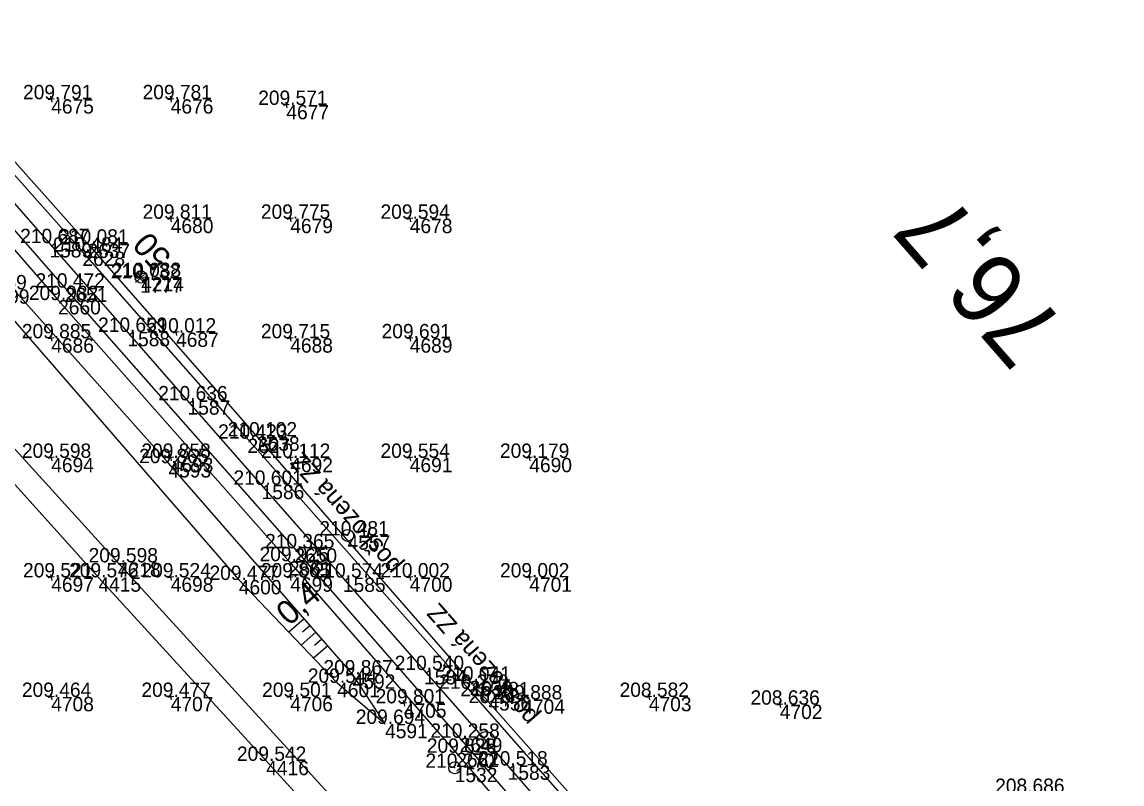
# Model space of a CAD drawing. Extents: x -556590 to -554855, y -1137918 to -1135717.
# Drawn here: x -555142.4 to -555050.4, y -1137077.3 to -1137013.5 of the extents above; entities that cross this region are included whole.
import ezdxf

# ---------------------------------------------------------------- set-up
doc = ezdxf.new("R2010")
doc.units = 0
for name, color, linetype in [('Vrstva 1', 7, 'Continuous'), ('Vrstva 11', 7, 'Continuous'), ('Vrstva 4', 7, 'Continuous'), ('Vrstva 48', 7, 'Continuous'), ('Vrstva 49', 7, 'Continuous'), ('Vrstva 50', 7, 'Continuous'), ('Vrstva 51', 7, 'Continuous'), ('Vrstva 60', 7, 'Continuous'), ('Vrstva 61', 7, 'Continuous'), ('Vrstva 7', 7, 'Continuous')]:
    doc.layers.add(name, color=color, linetype=linetype)

msp = doc.modelspace()

# ---------------------------------------------------------------- linework, layer by layer
at = {"layer": 'Vrstva 1'}
msp.add_lwpolyline([(-555050.414, -1137138.83), (-555056.682, -1137130.254), (-555062.877, -1137122.118), (-555068.951, -1137114.438), (-555075.468, -1137106.449), (-555082.42, -1137098.163), (-555087.974, -1137091.657), (-555094.849, -1137083.708), (-555101.808, -1137075.734), (-555108.81, -1137067.75), (-555115.592, -1137060.018), (-555122.396, -1137052.251), (-555128.594, -1137045.188), (-555133.626, -1137039.462), (-555140.146, -1137032.037), (-555146.394, -1137024.923)], dxfattribs=at)
at = {"layer": 'Vrstva 11'}
for p, q in [((-555132.809, -1137034.495), (-555132.145, -1137035.251)), ((-555132.061, -1137034.592), (-555132.763, -1137034.547)), ((-555131.987, -1137034.973), (-555132.414, -1137034.945))]:
    msp.add_line(p, q, dxfattribs=at)
msp.add_circle((-555132.477, -1137034.873), 0.503, dxfattribs=at)
msp.add_arc((-555132.477, -1137034.873), 0.503, 311.28684, 131.28684, dxfattribs=at)
at = {"layer": 'Vrstva 4'}
for points in [[(-555197.709, -1136962.437), (-555182.891, -1136979.591), (-555167.362, -1136997.627), (-555155.127, -1137011.646), (-555136.972, -1137032.08), (-555122.785, -1137048.208), (-555104.987, -1137068.646), (-555091.678, -1137083.676), (-555079.551, -1137098.027), (-555070.164, -1137109.439)], [(-555070.591, -1137109.654), (-555080.274, -1137097.941), (-555091.957, -1137084.274), (-555105.08, -1137069.321), (-555123.584, -1137048.396), (-555137.389, -1137032.746), (-555155.764, -1137012.076), (-555167.706, -1136998.175), (-555183.54, -1136980.02), (-555198.389, -1136963.208)], [(-555092.816, -1137089.456), (-555093.053, -1137088.239), (-555105.822, -1137073.42), (-555119.654, -1137057.568), (-555138.868, -1137035.761), (-555157.027, -1137015.002), (-555173.15, -1136997.195), (-555186.763, -1136981.447), (-555200.761, -1136965.356)], [(-555201.621, -1136965.878), (-555186.882, -1136982.839), (-555173.619, -1136998.021), (-555158.079, -1137015.373), (-555139.421, -1137036.799), (-555120.117, -1137058.648), (-555106.12, -1137074.669), (-555093.927, -1137088.885), (-555092.816, -1137089.456)]]:
    msp.add_lwpolyline(points, dxfattribs=at)
at = {"layer": 'Vrstva 48'}
for p, q in [((-555118.835, -1137063.462), (-555120.126, -1137064.588)), ((-555117.849, -1137064.593), (-555119.088, -1137065.673)), ((-555118.342, -1137064.027), (-555118.974, -1137064.579)), ((-555116.863, -1137065.723), (-555118.05, -1137066.759)), ((-555117.356, -1137065.158), (-555117.962, -1137065.687))]:
    msp.add_line(p, q, dxfattribs=at)
at = {"layer": 'Vrstva 49'}
for p, q in [((-555140.047, -1137019.754), (-555139.953, -1137020.246)), ((-555130.047, -1137019.754), (-555129.953, -1137020.246)), ((-555139.754, -1137019.953), (-555140.246, -1137020.047)), ((-555129.754, -1137019.953), (-555130.246, -1137020.047)), ((-555120.079, -1137020.43), (-555120.571, -1137020.524)), ((-555120.372, -1137020.231), (-555120.278, -1137020.723)), ((-555130.047, -1137029.754), (-555129.953, -1137030.246)), ((-555120.047, -1137029.754), (-555119.953, -1137030.246)), ((-555110.047, -1137029.754), (-555109.953, -1137030.246)), ((-555129.754, -1137029.953), (-555130.246, -1137030.047)), ((-555119.754, -1137029.953), (-555120.246, -1137030.047)), ((-555109.754, -1137029.953), (-555110.246, -1137030.047)), ((-555139.754, -1137039.953), (-555140.246, -1137040.047)), ((-555140.047, -1137039.754), (-555139.953, -1137040.246)), ((-555129.308, -1137039.467), (-555129.8, -1137039.561)), ((-555129.601, -1137039.268), (-555129.507, -1137039.76)), ((-555119.754, -1137039.953), (-555120.246, -1137040.047)), ((-555120.047, -1137039.754), (-555119.953, -1137040.246)), ((-555109.754, -1137039.953), (-555110.246, -1137040.047)), ((-555110.047, -1137039.754), (-555109.953, -1137040.246)), ((-555139.754, -1137049.953), (-555140.246, -1137050.047)), ((-555140.047, -1137049.754), (-555139.953, -1137050.246)), ((-555129.754, -1137049.953), (-555130.246, -1137050.047)), ((-555130.047, -1137049.754), (-555129.953, -1137050.246)), ((-555119.754, -1137049.953), (-555120.246, -1137050.047)), ((-555120.047, -1137049.754), (-555119.953, -1137050.246)), ((-555109.754, -1137049.953), (-555110.246, -1137050.047)), ((-555110.047, -1137049.754), (-555109.953, -1137050.246)), ((-555099.754, -1137049.953), (-555100.246, -1137050.047)), ((-555100.047, -1137049.754), (-555099.953, -1137050.246)), ((-555139.754, -1137059.953), (-555140.246, -1137060.047)), ((-555140.047, -1137059.754), (-555139.953, -1137060.246)), ((-555129.754, -1137059.953), (-555130.246, -1137060.047)), ((-555130.047, -1137059.754), (-555129.953, -1137060.246)), ((-555119.754, -1137059.953), (-555120.246, -1137060.047)), ((-555120.047, -1137059.754), (-555119.953, -1137060.246)), ((-555109.754, -1137059.953), (-555110.246, -1137060.047)), ((-555110.047, -1137059.754), (-555109.953, -1137060.246)), ((-555099.754, -1137059.953), (-555100.246, -1137060.047)), ((-555100.047, -1137059.754), (-555099.953, -1137060.246)), ((-555139.754, -1137069.953), (-555140.246, -1137070.047)), ((-555140.047, -1137069.754), (-555139.953, -1137070.246)), ((-555129.754, -1137069.953), (-555130.246, -1137070.047)), ((-555130.047, -1137069.754), (-555129.953, -1137070.246)), ((-555119.754, -1137069.953), (-555120.246, -1137070.047)), ((-555120.047, -1137069.754), (-555119.953, -1137070.246)), ((-555110.547, -1137070.291), (-555110.453, -1137070.783)), ((-555100.345, -1137070.16), (-555100.837, -1137070.254)), ((-555100.638, -1137069.961), (-555100.544, -1137070.453)), ((-555089.754, -1137069.953), (-555090.246, -1137070.047)), ((-555090.047, -1137069.754), (-555089.953, -1137070.246)), ((-555079.092, -1137070.401), (-555078.998, -1137070.893)), ((-555110.254, -1137070.49), (-555110.746, -1137070.584)), ((-555078.799, -1137070.6), (-555079.291, -1137070.694))]:
    msp.add_line(p, q, dxfattribs=at)
for points in [[(-555112.067, -1137072.254), (-555114.775, -1137068.117), (-555130.188, -1137050.444), (-555147.188, -1137031.407), (-555156.083, -1137021.917), (-555158.122, -1137020.767), (-555161.258, -1137019.606)], [(-555161.258, -1137019.606), (-555157.188, -1137022.91), (-555145.389, -1137035.904), (-555124.304, -1137060.218), (-555116.079, -1137068.82), (-555112.067, -1137072.254)]]:
    msp.add_lwpolyline(points, dxfattribs=at)
at = {"layer": 'Vrstva 50'}
for p, q in [((-555115.238, -1137056.45), (-555115.172, -1137056.526)), ((-555103.389, -1137069.98), (-555103.455, -1137069.904))]:
    msp.add_line(p, q, dxfattribs=at)
for centre in [(-555115.205, -1137056.488), (-555103.422, -1137069.942)]:
    msp.add_circle(centre, 0.5, dxfattribs=at)
at = {"layer": 'Vrstva 51'}
for points in [[(-555106.827, -1137103.209), (-555101.481, -1137098.096), (-555108.132, -1137090.546), (-555122.012, -1137075.348), (-555136.05, -1137059.997), (-555146.035, -1137048.936), (-555160.294, -1137033.391), (-555175.97, -1137016.16), (-555195.056, -1136995.091), (-555213.136, -1136975.387), (-555223.605, -1136963.802), (-555230.94, -1136955.939), (-555232.118, -1136955.037), (-555233.547, -1136954.632), (-555234.935, -1136954.442), (-555237.794, -1136954.661), (-555240.108, -1136957.322), (-555245.31, -1136962.604), (-555254.296, -1136971.783)], [(-555062.452, -1137139.044), (-555068.645, -1137131.182), (-555075.159, -1137122.841), (-555082.95, -1137112.848), (-555097.37, -1137094.105), (-555099.977, -1137096.599), (-555114.804, -1137080.276), (-555134.417, -1137058.746), (-555153.981, -1137037.247)]]:
    msp.add_lwpolyline(points, dxfattribs=at)
at = {"layer": 'Vrstva 60'}
for p, q in [((-555140, -1137020), (-555140, -1137020)), ((-555130, -1137020), (-555130, -1137020)), ((-555120.325, -1137020.477), (-555120.325, -1137020.477)), ((-555130, -1137030), (-555130, -1137030)), ((-555120, -1137030), (-555120, -1137030)), ((-555110, -1137030), (-555110, -1137030)), ((-555140.146, -1137032.037), (-555140.146, -1137032.037)), ((-555136.972, -1137032.08), (-555136.972, -1137032.08)), ((-555137.389, -1137032.746), (-555137.389, -1137032.746)), ((-555132.564, -1137034.992), (-555132.564, -1137034.992)), ((-555132.477, -1137034.873), (-555132.477, -1137034.873)), ((-555138.868, -1137035.761), (-555138.868, -1137035.761)), ((-555139.421, -1137036.799), (-555139.421, -1137036.799)), ((-555140, -1137040), (-555140, -1137040)), ((-555133.626, -1137039.462), (-555133.626, -1137039.462)), ((-555129.554, -1137039.514), (-555129.554, -1137039.514)), ((-555120, -1137040), (-555120, -1137040)), ((-555110, -1137040), (-555110, -1137040)), ((-555128.594, -1137045.188), (-555128.594, -1137045.188)), ((-555122.785, -1137048.208), (-555122.785, -1137048.208)), ((-555123.584, -1137048.396), (-555123.584, -1137048.396)), ((-555140, -1137050), (-555140, -1137050)), ((-555130, -1137050), (-555130, -1137050)), ((-555120, -1137050), (-555120, -1137050)), ((-555110, -1137050), (-555110, -1137050)), ((-555100, -1137050), (-555100, -1137050)), ((-555130.188, -1137050.444), (-555130.188, -1137050.444)), ((-555122.396, -1137052.251), (-555122.396, -1137052.251)), ((-555115.205, -1137056.488), (-555115.205, -1137056.488)), ((-555119.654, -1137057.568), (-555119.654, -1137057.568)), ((-555134.417, -1137058.746), (-555134.417, -1137058.746)), ((-555120.117, -1137058.648), (-555120.117, -1137058.648)), ((-555140, -1137060), (-555140, -1137060)), ((-555136.05, -1137059.997), (-555136.05, -1137059.997)), ((-555130, -1137060), (-555130, -1137060)), ((-555124.304, -1137060.218), (-555124.304, -1137060.218)), ((-555120, -1137060), (-555120, -1137060)), ((-555115.592, -1137060.018), (-555115.592, -1137060.018)), ((-555110, -1137060), (-555110, -1137060)), ((-555100, -1137060), (-555100, -1137060)), ((-555114.775, -1137068.117), (-555114.775, -1137068.117)), ((-555108.81, -1137067.75), (-555108.81, -1137067.75)), ((-555116.079, -1137068.82), (-555116.079, -1137068.82)), ((-555105.08, -1137069.321), (-555105.08, -1137069.321)), ((-555104.987, -1137068.646), (-555104.987, -1137068.646)), ((-555140, -1137070), (-555140, -1137070)), ((-555130, -1137070), (-555130, -1137070)), ((-555120, -1137070), (-555120, -1137070)), ((-555103.422, -1137069.942), (-555103.422, -1137069.942)), ((-555100.591, -1137070.207), (-555100.591, -1137070.207)), ((-555090, -1137070), (-555090, -1137070)), ((-555110.5, -1137070.537), (-555110.5, -1137070.537)), ((-555079.045, -1137070.647), (-555079.045, -1137070.647)), ((-555112.067, -1137072.254), (-555112.067, -1137072.254)), ((-555105.822, -1137073.42), (-555105.822, -1137073.42)), ((-555106.12, -1137074.669), (-555106.12, -1137074.669)), ((-555122.012, -1137075.348), (-555122.012, -1137075.348)), ((-555106.24, -1137075.93), (-555106.24, -1137075.93)), ((-555101.808, -1137075.734), (-555101.808, -1137075.734))]:
    msp.add_line(p, q, dxfattribs=at)
at = {"layer": 'Vrstva 7'}
for p, q in [((-555132.188, -1137034.662), (-555132.94, -1137035.322)), ((-555132.894, -1137034.616), (-555132.234, -1137035.368)), ((-555106.19, -1137075.93), (-555106.29, -1137075.93))]:
    msp.add_line(p, q, dxfattribs=at)
for centre, radius in [((-555103.638, -1137073.648), 0.75), ((-555106.24, -1137075.93), 0.5)]:
    msp.add_circle(centre, radius, dxfattribs=at)

# ---------------------------------------------------------------- texts
at = {"layer": 'Vrstva 11'}
msp.add_text('50', height=2, rotation=131.28684, dxfattribs=at).set_placement((-555129.845, -1137033.186))
at = {"layer": 'Vrstva 48'}
msp.add_text('0,4', height=2, rotation=41.09238, dxfattribs=at).set_placement((-555120.091, -1137064.129))
at = {"layer": 'Vrstva 50'}
for rotation, p in [(131.21881, (-555110.611, -1137058.976)), (131.25089, (-555099.178, -1137071.599))]:
    msp.add_text('poškozená ZZ', height=1.5, rotation=rotation, dxfattribs=at).set_placement(p)
at = {"layer": 'Vrstva 60'}
for s, p in [('4675', (-555140, -1137021.2)), ('4676', (-555130, -1137021.2)), ('4677', (-555120.325, -1137021.677)), ('4680', (-555130, -1137031.2)), ('4679', (-555120, -1137031.2)), ('4678', (-555110, -1137031.2)), ('1589', (-555140.146, -1137033.237)), ('2637', (-555136.972, -1137033.28)), ('2628', (-555137.389, -1137033.946)), ('1777', (-555132.564, -1137036.192)), ('4214', (-555132.477, -1137036.073)), ('4599', (-555145.389, -1137037.104)), ('2651', (-555138.868, -1137036.961)), ('2660', (-555139.421, -1137037.999)), ('4686', (-555140, -1137041.2)), ('1588', (-555133.626, -1137040.662)), ('4687', (-555129.554, -1137040.714)), ('4688', (-555120, -1137041.2)), ('4689', (-555110, -1137041.2)), ('1587', (-555128.594, -1137046.388)), ('2638', (-555122.785, -1137049.408)), ('2627', (-555123.584, -1137049.596)), ('4694', (-555140, -1137051.2)), ('4693', (-555130, -1137051.2)), ('4692', (-555120, -1137051.2)), ('4691', (-555110, -1137051.2)), ('4690', (-555100, -1137051.2)), ('4593', (-555130.188, -1137051.644)), ('1586', (-555122.396, -1137053.451)), ('4557', (-555115.205, -1137057.688)), ('2650', (-555119.654, -1137058.768)), ('4218', (-555134.417, -1137059.946)), ('2661', (-555120.117, -1137059.848)), ('4697', (-555140, -1137061.2)), ('4415', (-555136.05, -1137061.197)), ('4698', (-555130, -1137061.2)), ('4600', (-555124.304, -1137061.418)), ('4699', (-555120, -1137061.2)), ('1585', (-555115.592, -1137061.218)), ('4700', (-555110, -1137061.2)), ('4701', (-555100, -1137061.2)), ('4592', (-555114.775, -1137069.317)), ('1584', (-555108.81, -1137068.95)), ('4601', (-555116.079, -1137070.02)), ('2626', (-555105.08, -1137070.521)), ('2639', (-555104.987, -1137069.846)), ('4708', (-555140, -1137071.2)), ('4707', (-555130, -1137071.2)), ('4706', (-555120, -1137071.2)), ('4556', (-555103.422, -1137071.142)), ('4704', (-555100.591, -1137071.407)), ('4703', (-555090, -1137071.2)), ('4705', (-555110.5, -1137071.737)), ('4702', (-555079.045, -1137071.847)), ('4591', (-555112.067, -1137073.454)), ('2649', (-555105.822, -1137074.62)), ('2662', (-555106.12, -1137075.869)), ('4416', (-555122.012, -1137076.548)), ('1532', (-555106.24, -1137077.13)), ('1583', (-555101.808, -1137076.934))]:
    msp.add_text(s, height=1.2, dxfattribs=at).set_placement(p)
at = {"layer": 'Vrstva 61'}
for s, p in [('209.791', (-555142.357, -1137020)), ('209.781', (-555132.357, -1137020)), ('209.571', (-555122.682, -1137020.477)), ('209.811', (-555132.357, -1137030)), ('209.775', (-555122.456, -1137030)), ('209.594', (-555112.451, -1137030)), ('210.687', (-555142.598, -1137032.037)), ('210.484', (-555139.84, -1137032.746)), ('210.081', (-555139.329, -1137032.08)), ('210.732', (-555135.012, -1137034.992)), ('210.088', (-555134.931, -1137034.873)), ('209.669', (-555147.843, -1137035.904)), ('210.472', (-555141.316, -1137035.761)), ('209.982', (-555141.869, -1137036.799)), ('209.885', (-555142.456, -1137040)), ('210.659', (-555136.08, -1137039.462)), ('210.012', (-555132.002, -1137039.514)), ('209.715', (-555122.456, -1137040)), ('209.691', (-555112.357, -1137040)), ('210.636', (-555131.046, -1137045.188)), ('210.423', (-555126.036, -1137048.396)), ('210.102', (-555125.233, -1137048.208)), ('209.598', (-555142.454, -1137050)), ('209.865', (-555132.644, -1137050.444)), ('209.858', (-555132.454, -1137050)), ('210.112', (-555122.448, -1137050)), ('209.554', (-555112.451, -1137050)), ('209.179', (-555102.454, -1137050)), ('210.601', (-555124.753, -1137052.251)), ('210.481', (-555117.562, -1137056.488)), ('210.365', (-555122.11, -1137057.568)), ('209.598', (-555136.871, -1137058.746)), ('209.926', (-555122.569, -1137058.648)), ('209.521', (-555142.357, -1137060)), ('209.576', (-555138.502, -1137059.997)), ('209.524', (-555132.451, -1137060)), ('209.477', (-555126.756, -1137060.218)), ('209.865', (-555122.456, -1137060)), ('210.574', (-555118.043, -1137060.018)), ('210.002', (-555112.448, -1137060)), ('209.002', (-555102.448, -1137060)), ('210.540', (-555111.261, -1137067.75)), ('209.544', (-555118.53, -1137068.82)), ('209.867', (-555117.227, -1137068.117)), ('210.041', (-555107.344, -1137068.646)), ('210.270', (-555107.531, -1137069.321)), ('209.464', (-555142.451, -1137070)), ('209.477', (-555132.452, -1137070)), ('209.501', (-555122.357, -1137070)), ('209.801', (-555112.857, -1137070.537)), ('210.481', (-555105.779, -1137069.942)), ('209.888', (-555103.045, -1137070.207)), ('208.582', (-555092.448, -1137070)), ('208.636', (-555081.497, -1137070.647)), ('209.694', (-555114.518, -1137072.254)), ('210.258', (-555108.276, -1137073.42)), ('209.826', (-555108.572, -1137074.669)), ('209.542', (-555124.46, -1137075.348)), ('210.270', (-555108.691, -1137075.93)), ('210.518', (-555104.262, -1137075.734)), ('208.686', (-555061.025, -1137078.032))]:
    msp.add_text(s, height=1.2, dxfattribs=at).set_placement(p)
at = {"layer": 'Vrstva 7'}
msp.add_text('76,7', height=6, rotation=131.11157, dxfattribs=at).set_placement((-555055, -1137039))

doc.saveas('drawing.dxf')
